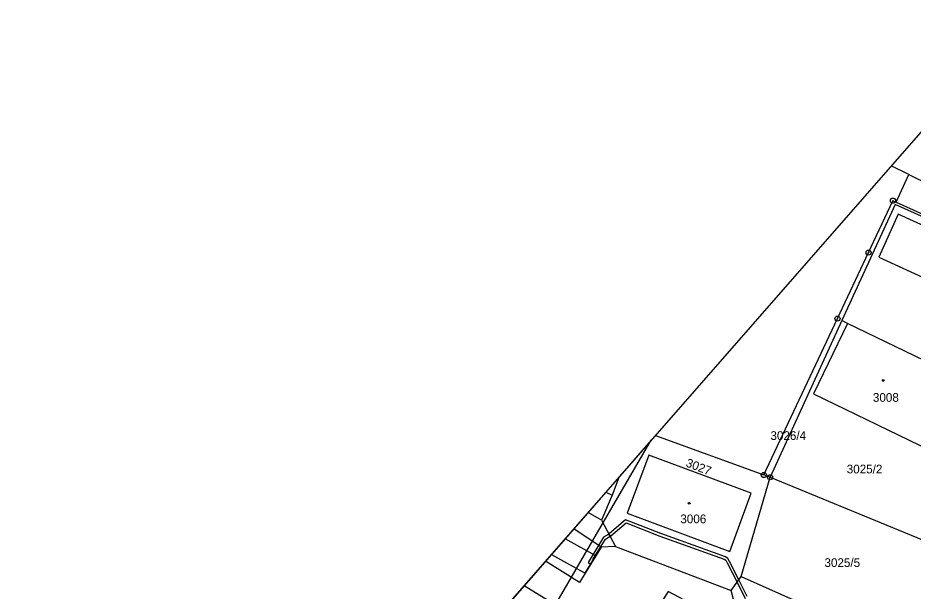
# Model space of a CAD drawing. Extents: x -620475 to -619963, y -1123010 to -1122510.
# Drawn here: x -620474.6 to -620300.1, y -1122621.9 to -1122510.1 of the extents above; entities that cross this region are included whole.
import ezdxf

# ---------------------------------------------------------------- set-up
doc = ezdxf.new("R2010")
doc.units = 0
for name, color, linetype in [('HranDP', 7, 'Continuous'), ('Hranice parcel', 7, 'Continuous'), ('Parcelní čísla', 7, 'Continuous'), ('Rámečky', 7, 'Continuous'), ('Rámečky-tisk', 7, 'Continuous'), ('Vnitřní kresba', 7, 'Continuous'), ('Věcná břemena k části', 7, 'Continuous'), ('Značky bodu BP', 7, 'Continuous'), ('Značky budov', 7, 'Continuous')]:
    doc.layers.add(name, color=color, linetype=linetype)

msp = doc.modelspace()

# ---------------------------------------------------------------- linework, layer by layer
at = {"layer": 'HranDP'}
msp.add_line((-620358.11, -1122613.18), (-620335.54, -1122621.75), dxfattribs=at)
for points in [[(-620358.11, -1122613.18), (-620360.91, -1122613.28), (-620361.94, -1122614.97), (-620364.03, -1122618.38), (-620365.14, -1122620.19), (-620371.77, -1122616.05)], [(-620297.09, -1122645.35), (-620318.55, -1122633.1), (-620335.09, -1122623.49), (-620335.54, -1122621.75)]]:
    msp.add_lwpolyline(points, dxfattribs=at)
at = {"layer": 'Hranice parcel'}
for p, q in [((-620300.93, -1122540.63), (-620304.33, -1122538.95)), ((-620303.36, -1122546.01), (-620300.93, -1122540.63)), ((-620303.56, -1122546.46), (-620313.95, -1122569.11)), ((-620269.23, -1122562), (-620303.56, -1122546.46)), ((-620303.36, -1122546.01), (-620269.35, -1122561.48)), ((-620313.95, -1122569.11), (-620327.97, -1122599.65)), ((-620312.88, -1122569.65), (-620313.95, -1122569.11)), ((-620350.31, -1122591.51), (-620329.18, -1122599.21)), ((-620357.46, -1122599.69), (-620358.78, -1122603.15)), ((-620333.59, -1122619.01), (-620327.97, -1122599.65)), ((-620327.97, -1122599.65), (-620329.18, -1122599.21)), ((-620327.97, -1122599.65), (-620295.2, -1122613.12)), ((-620358.78, -1122603.15), (-620360.83, -1122608.03)), ((-620359.97, -1122602.56), (-620358.78, -1122603.15)), ((-620360.83, -1122608.03), (-620363.43, -1122606.52)), ((-620360.83, -1122608.03), (-620358.11, -1122613.18)), ((-620358.11, -1122613.18), (-620335.54, -1122621.75)), ((-620335.54, -1122621.75), (-620333.59, -1122619.01))]:
    msp.add_line(p, q, dxfattribs=at)
for points in [[(-620300.93, -1122540.63), (-620280.94, -1122550.46), (-620278.42, -1122551.7)], [(-620329.18, -1122599.21), (-620314.82, -1122568.71), (-620308.76, -1122555.84), (-620304, -1122545.72), (-620303.36, -1122546.01)], [(-620306.78, -1122556.75), (-620268.73, -1122574.18), (-620264.84, -1122565.74), (-620303, -1122548.37), (-620306.78, -1122556.75)], [(-620312.88, -1122569.65), (-620319.52, -1122583.38), (-620298.85, -1122593.38), (-620295.91, -1122594.79), (-620292.71, -1122588.19)], [(-620292.71, -1122588.19), (-620289.27, -1122581.08), (-620292.27, -1122579.64), (-620312.88, -1122569.65)], [(-620335.8, -1122614.14), (-620331.64, -1122602.77), (-620351.59, -1122595.35), (-620355.84, -1122606.66), (-620335.8, -1122614.14)], [(-620358.11, -1122613.18), (-620360.91, -1122613.28), (-620361.94, -1122614.97), (-620364.03, -1122618.38), (-620365.14, -1122620.19), (-620371.77, -1122616.05)], [(-620333.59, -1122619.01), (-620307.23, -1122630.79), (-620302.25, -1122634.43)], [(-620296.23, -1122649.3), (-620347.83, -1122621.96), (-620355.23, -1122633.54), (-620375.94, -1122620.82)], [(-620297.09, -1122645.35), (-620318.55, -1122633.1), (-620335.09, -1122623.49), (-620335.54, -1122621.75)]]:
    msp.add_lwpolyline(points, dxfattribs=at)
at = {"layer": 'Rámečky'}
msp.add_lwpolyline([(-620279.07, -1122510.07), (-620474.61, -1122733.62), (-620158.49, -1123010.14)], dxfattribs=at)
at = {"layer": 'Rámečky-tisk'}
msp.add_line((-620351.12, -1122592.44), (-620471.94, -1122730.56), dxfattribs=at)
for points in [[(-620279.07, -1122510.07), (-620474.61, -1122733.62), (-620158.49, -1123010.14)], [(-620471.94, -1122730.56), (-620441.66, -1122748.16), (-620351.12, -1122592.44)]]:
    msp.add_lwpolyline(points, dxfattribs=at)
at = {"layer": 'Vnitřní kresba'}
msp.add_line((-620360.91, -1122613.28), (-620366.2, -1122609.68), dxfattribs=at)
at = {"layer": 'Věcná břemena k části'}
msp.add_line((-620367.91, -1122611.63), (-620370.6, -1122614.71), dxfattribs=at)
for points in [[(-620332.41, -1122622.94), (-620334.05, -1122619.66), (-620335.86, -1122616.06), (-620336.23, -1122615.51), (-620336.65, -1122615.18), (-620349.27, -1122610.65), (-620356.14, -1122607.95), (-620359.28, -1122610.65), (-620359.41, -1122610.73), (-620359.17, -1122611.17), (-620358.98, -1122611.05), (-620356.04, -1122608.53), (-620349.45, -1122611.11), (-620336.89, -1122615.62), (-620336.61, -1122615.85), (-620336.3, -1122616.32), (-620334.39, -1122620.13), (-620332.8, -1122623.28)], [(-620370.6, -1122614.71), (-620364.03, -1122618.38), (-620362.52, -1122615.91), (-620361.94, -1122614.97), (-620367.91, -1122611.63)]]:
    msp.add_lwpolyline(points, dxfattribs=at)
msp.add_lwpolyline([(-620362.93, -1122616.59), (-620362.41, -1122615.74), (-620362.5, -1122615.69), (-620360.06, -1122611.71), (-620359.17, -1122611.17), (-620359.41, -1122610.73), (-620360.42, -1122611.35), (-620363.45, -1122616.28)], close=True, dxfattribs=at)
at = {"layer": 'Značky bodu BP'}
for centre, radius in [((-620304, -1122545.72), 0.5), ((-620304, -1122545.72), 0.0303), ((-620308.76, -1122555.84), 0.5), ((-620308.76, -1122555.84), 0.0303), ((-620314.82, -1122568.71), 0.5), ((-620314.82, -1122568.71), 0.0303), ((-620329.18, -1122599.21), 0.5), ((-620329.18, -1122599.21), 0.0303), ((-620327.97, -1122599.65), 0.5), ((-620327.97, -1122599.65), 0.0303)]:
    msp.add_circle(centre, radius, dxfattribs=at)
at = {"layer": 'Značky budov'}
for centre in [(-620305.9, -1122580.76), (-620343.74, -1122604.73)]:
    msp.add_circle(centre, 0.175, dxfattribs=at)

# ---------------------------------------------------------------- texts
at = {"layer": 'Parcelní čísla'}
for s, p in [('3008', (-620307.92, -1122584.94)), ('3026/4', (-620327.89, -1122592.38)), ('3025/2', (-620313.02, -1122598.9)), ('3006', (-620345.46, -1122608.62)), ('3025/5', (-620317.36, -1122617.15))]:
    msp.add_text(s, height=1.7, dxfattribs=at).set_placement(p)
msp.add_text('3027', height=1.7, rotation=339, dxfattribs=at).set_placement((-620344.54, -1122597.51))

doc.saveas('drawing.dxf')
